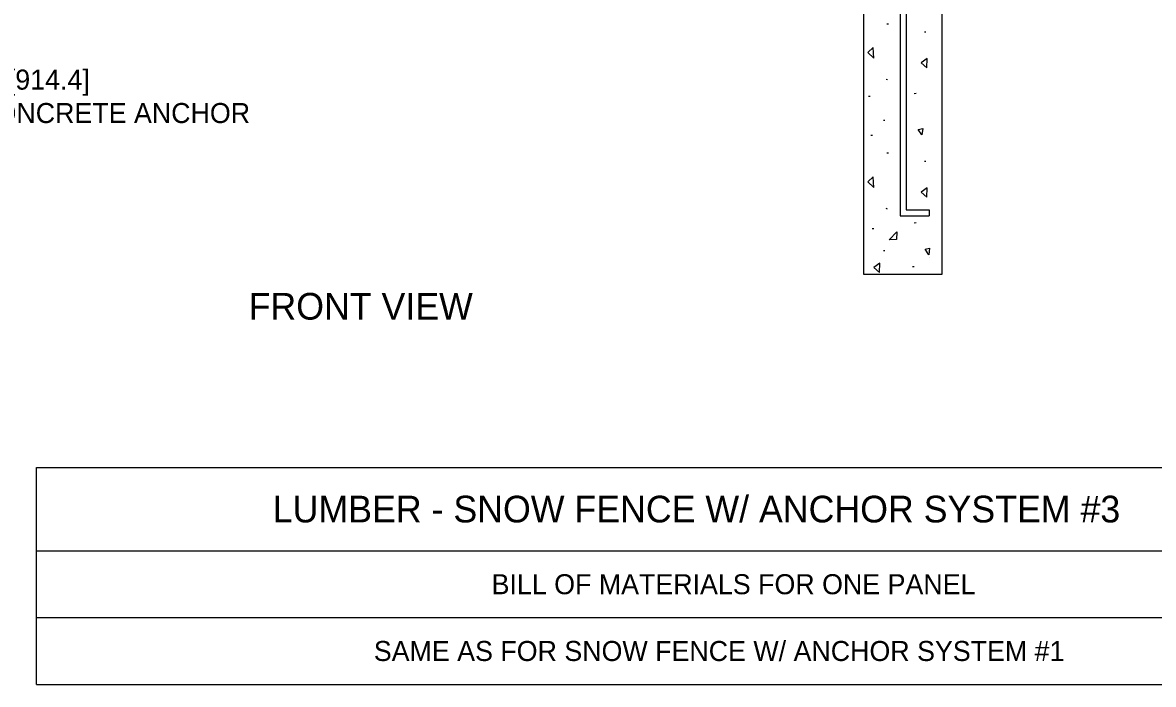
# Model space of a CAD drawing. Extents: x 49991.4 to 50021, y 49987.6 to 50011.4.
# Drawn here: x 50011.41 to 50014.797, y 49994.035 to 49996.017 of the extents above; entities that cross this region are included whole.
import ezdxf

# ---------------------------------------------------------------- set-up
doc = ezdxf.new("R2010")
doc.units = 0
doc.layers.add('Level 1', color=7, linetype='Continuous')
doc.layers.add('Level 2', color=7, linetype='Continuous')

msp = doc.modelspace()

# ---------------------------------------------------------------- linework, layer by layer
at = {"layer": 'Level 1'}
for p, q in [((50014.0385, 49996.5951), (50014.0385, 49995.438)), ((50014.0567, 49996.5951), (50014.0567, 49995.4565)), ((50013.9299, 49995.263), (50013.9299, 49996.2404)), ((50014.1637, 49996.2404), (50014.1637, 49995.263)), ((50014.0041, 49996.0128), (50013.9991, 49996.0128)), ((50014.1156, 49995.9887), (50014.1117, 49995.9883)), ((50014.0006, 49995.8455), (50013.9971, 49995.847)), ((50014.0861, 49995.8049), (50014.0809, 49995.8038)), ((50013.9485, 49995.7958), (50013.9435, 49995.7958)), ((50013.9931, 49995.7239), (50013.9888, 49995.7239)), ((50013.9558, 49995.6793), (50013.951, 49995.6793)), ((50014.0041, 49995.6256), (50013.9991, 49995.6256)), ((50014.1156, 49995.6013), (50014.1117, 49995.6013)), ((50014.0006, 49995.4583), (50013.9971, 49995.46)), ((50014.0385, 49995.438), (50014.126, 49995.438)), ((50014.0567, 49995.4565), (50014.126, 49995.4565)), ((50014.126, 49995.4565), (50014.126, 49995.438)), ((50013.9601, 49995.399), (50013.9549, 49995.399)), ((50014.0861, 49995.4174), (50014.0809, 49995.4168)), ((50013.9931, 49995.334), (50013.9888, 49995.334)), ((50014.1254, 49995.314), (50014.1254, 49995.314)), ((50014.1637, 49995.263), (50013.9299, 49995.263)), ((50014.0807, 49995.2854), (50014.0759, 49995.2854))]:
    msp.add_line(p, q, dxfattribs=at)
for points in [[(50013.9581, 49995.9426), (50013.9417, 49995.9275), (50013.9602, 49995.9101)], [(50014.1191, 49995.9097), (50014.1015, 49995.897), (50014.1183, 49995.8817)], [(50014.1061, 49995.7001), (50014.1036, 49995.6805), (50014.0924, 49995.6972)], [(50013.9581, 49995.5556), (50013.9417, 49995.5399), (50013.9602, 49995.5231)], [(50014.1191, 49995.5226), (50014.1015, 49995.5095), (50014.1183, 49995.4946)], [(50014.0274, 49995.3678), (50014.0054, 49995.3668), (50014.0289, 49995.3907)], [(50014.1269, 49995.3415), (50014.1244, 49995.3219), (50014.1132, 49995.3385)], [(50013.9776, 49995.2967), (50013.96, 49995.2836), (50013.9767, 49995.2687)]]:
    msp.add_lwpolyline(points, close=True, dxfattribs=at)
at = {"layer": 'Level 2'}
for p, q in [((50011.4523, 49994.6852), (50015.9523, 49994.6852)), ((50011.4523, 49994.0352), (50011.4523, 49994.6852)), ((50011.4523, 49994.4352), (50015.9523, 49994.4352)), ((50011.4523, 49994.2352), (50015.9523, 49994.2352)), ((50011.4523, 49994.0352), (50015.9523, 49994.0352))]:
    msp.add_line(p, q, dxfattribs=at)

# ---------------------------------------------------------------- texts
for s, height, p in [('8" [203.2] DIA. x 3\'-0" [914.4] ', 0.06, (50010.5803, 49995.8163)), ('CLASS GENERAL CONCRETE ANCHOR', 0.06, (50010.5803, 49995.7163)), ('FRONT VIEW', 0.08, (50012.0872, 49995.1276)), ('LUMBER - SNOW FENCE W/ ANCHOR SYSTEM #3', 0.08, (50012.1597, 49994.5202)), ('BILL OF MATERIALS FOR ONE PANEL', 0.06, (50012.8151, 49994.3052)), ('SAME AS FOR SNOW FENCE W/ ANCHOR SYSTEM #1', 0.06, (50012.4623, 49994.1052))]:
    msp.add_text(s, height=height, dxfattribs=at).set_placement(p)

doc.saveas('drawing.dxf')
